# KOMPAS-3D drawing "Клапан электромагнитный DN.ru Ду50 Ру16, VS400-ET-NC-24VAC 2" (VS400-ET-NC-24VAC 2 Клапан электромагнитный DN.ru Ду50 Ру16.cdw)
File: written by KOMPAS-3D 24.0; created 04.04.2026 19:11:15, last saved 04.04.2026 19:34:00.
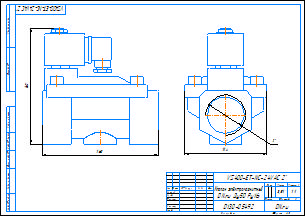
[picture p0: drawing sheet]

Document properties: c3d_UniqueCompID: ef56311e-7521-43dc-8291-0e6108b3d81d; Обозначение: VS400-ET-NC-220VAC 2; Наименование: Клапан электромагнитный DN.ru Ду50 Ру16; Автор: artio; Класс точности: c; Знак неуказанной шероховатости: Шероховатость не задана; Рассекать на разрезах: Да; c3d_UniqueCompID: ef56311e-7521-43dc-8291-0e6108b3d81d; Обозначение: VS400-ET-NC-220VAC 1; Наименование: Клапан электромагнитный DN.ru Ду25 Ру16; Автор: artio; Класс точности: c; Знак неуказанной шероховатости: Шероховатость не задана; Рассекать на разрезах: Да; c3d_UniqueCompID: ef56311e-7521-43dc-8291-0e6108b3d81d; Обозначение: VS400-ET-NC-220VAC 1-2; Наименование: Клапан электромагнитный DN.ru Ду15 Ру16; Автор: artio; Класс точности: c; Знак неуказанной шероховатости: Шероховатость не задана; Рассекать на разрезах: Да; c3d_UniqueCompID: ef56311e-7521-43dc-8291-0e6108b3d81d; Обозначение: VS400-ET-NC-220VAC 3-4; Наименование: Клапан электромагнитный DN.ru Ду20 Ру16; Автор: artio; Класс точности: c; Знак неуказанной шероховатости: Шероховатость не задана; Рассекать на разрезах: Да; c3d_UniqueCompID: ef56311e-7521-43dc-8291-0e6108b3d81d; Обозначение: VS400-ET-NC-220VAC 1 1-4; Наименование: Клапан электромагнитный DN.ru Ду32 Ру16; Автор: artio; Класс точности: c; Знак неуказанной шероховатости: Шероховатость не задана; Рассекать на разрезах: Да; c3d_UniqueCompID: ef56311e-7521-43dc-8291-0e6108b3d81d; Обозначение: VS400-ET-NC-220VAC 3-8; Наименование: Клапан электромагнитный DN.ru Ду10 Ру16; Автор: artio; Класс точности: c; Знак неуказанной шероховатости: Шероховатость не задана; Рассекать на разрезах: Да; c3d_UniqueCompID: ef56311e-7521-43dc-8291-0e6108b3d81d; Обозначение: VS400-ET-NC-220VAC 1 1-2; Наименование: Клапан электромагнитный DN.ru Ду40 Ру16; Автор: artio; Класс точности: c; Знак неуказанной шероховатости: Шероховатость не задана; Рассекать на разрезах: Да; Автор: artio; Форматы листов документа: A3; Полное имя файла: VS400-ET-NC-24VAC 2 Клапан электромагнитный DN.ru Ду50 Ру16.m3d; Масса: 3.509; Наименование: Клапан электромагнитный DN.ru Ду50 Ру16; Количество листов документа: 1; Примечание: D130-05492

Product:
- Body: Тело 1  | qty 1
    Масса: 7.119215
- Part/product: Клапан электромагнитный DN.ru Ду50 Ру16  | designation VS400-ET-NC-24VAC 2
    Масса: 3.509
    Раздел спецификации: Прочие изделия
    Примечание: D130-05492
    additional columns: ef56311e-7521-43dc-8291-0e6108b3d81d; VS400-ET-NC-220VAC 2; artio; c; Шероховатость не задана; Да

Views: Вид 1, Спереди
Referenced files in C:\Users\artio\OneDrive\Рабочий стол\Клапан электромагнитный DN.ru\VS400-ET-NC\VS400-ET-NC-24VDC\: VS400-ET-NC-24VDC 3-8 Клапан электромагнитный DN.ru Ду10 Ру16.m3d
Referenced files in C:\Users\artio\OneDrive\Рабочий стол\Клапан электромагнитный DN.ru\VS400\VS400-ET-NC\VS400-ET-NC-24VAC\Ду50\: VS400-ET-NC-24VAC 2 Клапан электромагнитный DN.ru Ду50 Ру16.m3d
Referenced files in C:\Users\artio\OneDrive\Рабочий стол\Клапан электромагнитный DN.ru\VS400-ET-NC\: VS400-ET-NC-24VDC 3-8 Клапан электромагнитный DN.ru Ду10 Ру16.cdw
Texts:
  VS400-ET-NC-24VAC 2
  Клапан электромагнитный
  DN.ru Ду50 Ру16
  VS400-ET-NC-24VAC 2"
  VS400-ET-NC-24VAC 2"-
  Клапан электромагнитный DN.ru Ду50 Ру16
  VS400-ET-NC-24VAC 2 Клапан электромагнитный DN.ru Ду50 Ру16
Dimensions and other numbers on the sheet: 0; 3; 2; 4; 114; 1:1; 1; 3,51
